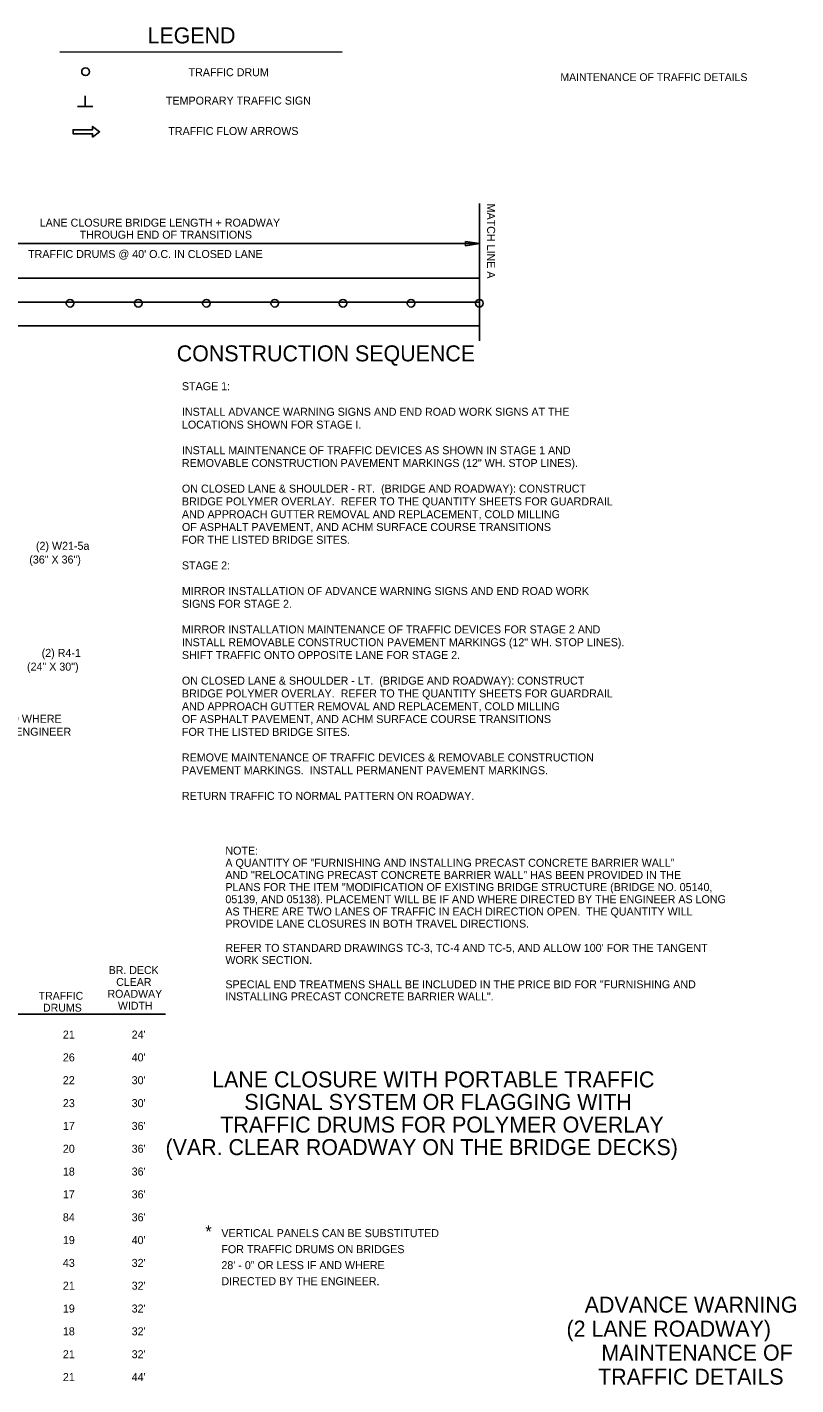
# Model space of a CAD drawing. Extents: x 1927831 to 1930787, y 596452 to 597699.
# Drawn here: x 1928834 to 1929411, y 596676 to 597694 of the extents above; entities that cross this region are included whole.
import ezdxf

# ---------------------------------------------------------------- set-up
doc = ezdxf.new("R2010")
doc.units = 0
for name, color, linetype in [('Default', 7, 'Continuous'), ('R_Annotation', 7, 'Continuous'), ('R_Border', 7, 'Continuous'), ('R_MOT', 7, 'Continuous')]:
    doc.layers.add(name, color=color, linetype=linetype)

msp = doc.modelspace()

# ---------------------------------------------------------------- linework, layer by layer
at = {"layer": 'Default'}
for p, q in [((1929173.7, 597561.6), (1929173.7, 597458.6)), ((1929173.7, 597531.6), (1928729.3, 597531.6)), ((1929163.2, 597530), (1929163.2, 597533.1)), ((1929163.2, 597533.1), (1929173.7, 597531.6)), ((1929173.7, 597531.6), (1929163.2, 597530)), ((1928044.8, 597505.6), (1929173.7, 597505.6)), ((1927908.3, 597487.8), (1929173.7, 597487.8)), ((1928044.8, 597470), (1929173.7, 597470))]:
    msp.add_line(p, q, dxfattribs=at)
for centre in [(1928878.1, 597660.5), (1928866.5, 597486.9), (1928917.7, 597486.9), (1928968.8, 597486.9), (1929020, 597486.9), (1929071.2, 597486.9), (1929122.3, 597486.9), (1929173.5, 597486.9)]:
    msp.add_circle(centre, 2.88, dxfattribs=at)
at = {"layer": 'R_Annotation'}
for p, q in [((1928858.7, 597675.1), (1929070.6, 597675.3)), ((1928877.9, 597634.6), (1928877.9, 597642.5)), ((1928883.6, 597634.5), (1928872.1, 597634.5)), ((1928634.2, 596953.7), (1928938.1, 596953.7))]:
    msp.add_line(p, q, dxfattribs=at)
at = {"layer": 'R_MOT'}
msp.add_lwpolyline([(1928883.4, 597611.5), (1928888.6, 597615.5), (1928883.4, 597619.5), (1928883.4, 597617), (1928868.7, 597617), (1928868.7, 597614), (1928883.4, 597614)], close=True, dxfattribs=at)

# ---------------------------------------------------------------- texts
at = {"layer": 'Default'}
for s, height, rotation, p in [('MATCH LINE A', 6, 270, (1929179.3, 597561.6)), ('LANE CLOSURE BRIDGE LENGTH + ROADWAY ', 6, 360, (1928843.7, 597544.3)), ('THROUGH END OF TRANSITIONS', 6, 360, (1928873.7, 597535.3)), ("TRAFFIC DRUMS @ 40' O.C. IN CLOSED LANE", 6, 360, (1928835, 597520.8)), ('LANE CLOSURE WITH PORTABLE TRAFFIC ', 12, 360, (1928973.1, 596898.9)), ('SIGNAL SYSTEM OR FLAGGING WITH ', 12, 360, (1928997.2, 596882)), ('TRAFFIC DRUMS FOR POLYMER OVERLAY', 12, 360, (1928979.2, 596865)), ('(VAR. CLEAR ROADWAY ON THE BRIDGE DECKS)', 12, 360, (1928938.1, 596848.1))]:
    msp.add_text(s, height=height, rotation=rotation, dxfattribs=at).set_placement(p)
at = {"layer": 'R_Annotation'}
for s, height, rotation, p in [('LEGEND', 12, 0.0388, (1928924.6, 597681.7)), ('TRAFFIC DRUM', 6, 0.0388, (1928955.4, 597657.1)), ('TEMPORARY TRAFFIC SIGN', 6, 0.0388, (1928938.4, 597635.8)), ('TRAFFIC FLOW ARROWS', 6, 0.0388, (1928940.2, 597613)), ('CONSTRUCTION SEQUENCE', 12, 360, (1928946.5, 597443.3)), ('STAGE 1:', 6, 360, (1928950.4, 597421.7)), ('INSTALL ADVANCE WARNING SIGNS AND END ROAD WORK SIGNS AT THE', 6, 360, (1928950.4, 597402.5)), ('LOCATIONS SHOWN FOR STAGE I.  ', 6, 360, (1928950.4, 597392.9)), ('INSTALL MAINTENANCE OF TRAFFIC DEVICES AS SHOWN IN STAGE 1 AND', 6, 360, (1928950.4, 597373.7)), ('REMOVABLE CONSTRUCTION PAVEMENT MARKINGS (12" WH. STOP LINES). ', 6, 360, (1928950.4, 597364.1)), ('ON CLOSED LANE & SHOULDER - RT.  (BRIDGE AND ROADWAY): CONSTRUCT', 6, 360, (1928950.4, 597344.9)), ('AND APPROACH GUTTER REMOVAL AND REPLACEMENT, COLD MILLING', 6, 360, (1928950.4, 597325.7)), ('BRIDGE POLYMER OVERLAY.  REFER TO THE QUANTITY SHEETS FOR GUARDRAIL', 6, 360, (1928950.4, 597335.3)), ('OF ASPHALT PAVEMENT, AND ACHM SURFACE COURSE TRANSITIONS', 6, 360, (1928950.4, 597316.1)), ('FOR THE LISTED BRIDGE SITES.', 6, 360, (1928950.4, 597306.5)), ('(2) W21-5a', 6, 360, (1928840.9, 597302)), ('(36" X 36")', 6, 360, (1928835.9, 597291.7)), ('STAGE 2:', 6, 360, (1928950.4, 597287.3)), ('MIRROR INSTALLATION OF ADVANCE WARNING SIGNS AND END ROAD WORK', 6, 360, (1928950.4, 597268.1)), ('SIGNS FOR STAGE 2.  ', 6, 360, (1928950.4, 597258.5)), ('MIRROR INSTALLATION MAINTENANCE OF TRAFFIC DEVICES FOR STAGE 2 AND', 6, 360, (1928950.4, 597239.3)), ('INSTALL REMOVABLE CONSTRUCTION PAVEMENT MARKINGS (12" WH. STOP LINES).', 6, 360, (1928950.4, 597229.7)), ('(2) R4-1', 6, 360, (1928845.2, 597221.7)), ('SHIFT TRAFFIC ONTO OPPOSITE LANE FOR STAGE 2.', 6, 360, (1928950.4, 597220.1)), ('(24" X 30")', 6, 360, (1928834.2, 597211.4)), ('ON CLOSED LANE & SHOULDER - LT.  (BRIDGE AND ROADWAY): CONSTRUCT', 6, 360, (1928950.4, 597200.9)), ('BRIDGE POLYMER OVERLAY.  REFER TO THE QUANTITY SHEETS FOR GUARDRAIL', 6, 360, (1928950.4, 597191.3)), ('AND APPROACH GUTTER REMOVAL AND REPLACEMENT, COLD MILLING', 6, 360, (1928950.4, 597181.7)), ('TO BE USED IF AND WHERE', 6, 360, (1928751, 597172.3)), ('OF ASPHALT PAVEMENT, AND ACHM SURFACE COURSE TRANSITIONS', 6, 360, (1928950.4, 597172.1)), ('DIRECTED BY THE ENGINEER', 6, 360, (1928751, 597162.6)), ('FOR THE LISTED BRIDGE SITES.', 6, 360, (1928950.4, 597162.5)), ('REMOVE MAINTENANCE OF TRAFFIC DEVICES & REMOVABLE CONSTRUCTION', 6, 360, (1928950.4, 597143.3)), ('PAVEMENT MARKINGS.  INSTALL PERMANENT PAVEMENT MARKINGS.', 6, 360, (1928950.4, 597133.7)), ('RETURN TRAFFIC TO NORMAL PATTERN ON ROADWAY. ', 6, 360, (1928950.4, 597114.5)), ('NOTE:', 6, 360, (1928983, 597073.4)), ('A QUANTITY OF "FURNISHING AND INSTALLING PRECAST CONCRETE BARRIER WALL" ', 6, 360, (1928983, 597064.3)), ('AND "RELOCATING PRECAST CONCRETE BARRIER WALL" HAS BEEN PROVIDED IN THE ', 6, 360, (1928983, 597055.2)), ('PLANS FOR THE ITEM "MODIFICATION OF EXISTING BRIDGE STRUCTURE (BRIDGE NO. 05140,', 6, 360, (1928983, 597046.1)), ('05139, AND 05138). PLACEMENT WILL BE IF AND WHERE DIRECTED BY THE ENGINEER AS LONG ', 6, 360, (1928983, 597037)), ('AS THERE ARE TWO LANES OF TRAFFIC IN EACH DIRECTION OPEN.  THE QUANTITY WILL', 6, 360, (1928983, 597027.8)), ('PROVIDE LANE CLOSURES IN BOTH TRAVEL DIRECTIONS.', 6, 360, (1928983, 597018.7)), ("REFER TO STANDARD DRAWINGS TC-3, TC-4 AND TC-5, AND ALLOW 100' FOR THE TANGENT", 6, 360, (1928983, 597000.5)), ('WORK SECTION.', 6, 360, (1928983, 596991.4)), ('BR. DECK ', 5.93, 360, (1928895.5, 596983.9)), ('CLEAR', 5.93, 360, (1928901.1, 596975)), ('SPECIAL END TREATMENS SHALL BE INCLUDED IN THE PRICE BID FOR "FURNISHING AND', 6, 360, (1928983, 596973.2)), ('TRAFFIC ', 5.93, 360, (1928842.9, 596964.6)), ('ROADWAY ', 5.93, 360, (1928894.6, 596966.1)), ('INSTALLING PRECAST CONCRETE BARRIER WALL".', 6, 360, (1928983, 596964.1)), ('DRUMS', 5.93, 360, (1928846.2, 596955.7)), ('WIDTH', 5.93, 360, (1928902.4, 596957.2)), ('21', 6, 360, (1928861.1, 596935.5)), ("24'", 6, 360, (1928912.7, 596935.5)), ('26', 6, 360, (1928861.1, 596918.4)), ("40'", 6, 360, (1928912.7, 596918.4)), ('22', 6, 360, (1928861.1, 596901.3)), ("30'", 6, 360, (1928912.7, 596901.3)), ('23', 6, 360, (1928861.1, 596884.1)), ("30'", 6, 360, (1928912.7, 596884.1)), ('17', 6, 360, (1928861.1, 596867)), ("36'", 6, 360, (1928912.7, 596867)), ('20', 6, 360, (1928861.1, 596849.9)), ("36'", 6, 360, (1928912.7, 596849.9)), ('18', 6, 360, (1928861.1, 596832.8)), ("36'", 6, 360, (1928912.7, 596832.8)), ('17', 6, 360, (1928861.1, 596815.7)), ("36'", 6, 360, (1928912.7, 596815.7)), ('84', 6, 360, (1928861.1, 596798.5)), ("36'", 6, 360, (1928912.7, 596798.5)), ('*', 9, 360, (1928968, 596786.4)), ('VERTICAL PANELS CAN BE SUBSTITUTED ', 6, 360, (1928980, 596786.6)), ('19', 6, 360, (1928861.1, 596781.4)), ("40'", 6, 360, (1928912.7, 596781.4)), ('FOR TRAFFIC DRUMS ON BRIDGES ', 6, 360, (1928980, 596774.6)), ('43', 6, 360, (1928861.1, 596764.3)), ("32'", 6, 360, (1928912.7, 596764.3)), ('28\' - 0" OR LESS IF AND WHERE ', 6, 360, (1928980, 596762.6)), ('21', 6, 360, (1928861.1, 596747.2)), ("32'", 6, 360, (1928912.7, 596747.2)), ('DIRECTED BY THE ENGINEER.', 6, 360, (1928980, 596750.6)), ('ADVANCE WARNING', 12, 360, (1929252.5, 596730)), ('19', 6, 360, (1928861.1, 596730.1)), ("32'", 6, 360, (1928912.7, 596730.1)), (' (2 LANE ROADWAY) ', 12, 360, (1929234.4, 596712)), ('18', 6, 360, (1928861.1, 596713)), ("32'", 6, 360, (1928912.7, 596713)), ('21', 6, 360, (1928861.1, 596695.8)), ("32'", 6, 360, (1928912.7, 596695.8)), ('MAINTENANCE OF ', 12, 360, (1929265, 596694)), ('21', 6, 360, (1928861.1, 596678.7)), ("44'", 6, 360, (1928912.7, 596678.7)), ('TRAFFIC DETAILS', 12, 360, (1929262.6, 596676))]:
    msp.add_text(s, height=height, rotation=rotation, dxfattribs=at).set_placement(p)
at = {"layer": 'R_Border'}
msp.add_text('MAINTENANCE OF TRAFFIC DETAILS', height=5.862, rotation=360, dxfattribs=at).set_placement((1929234.3, 597653.5))

doc.saveas('drawing.dxf')
